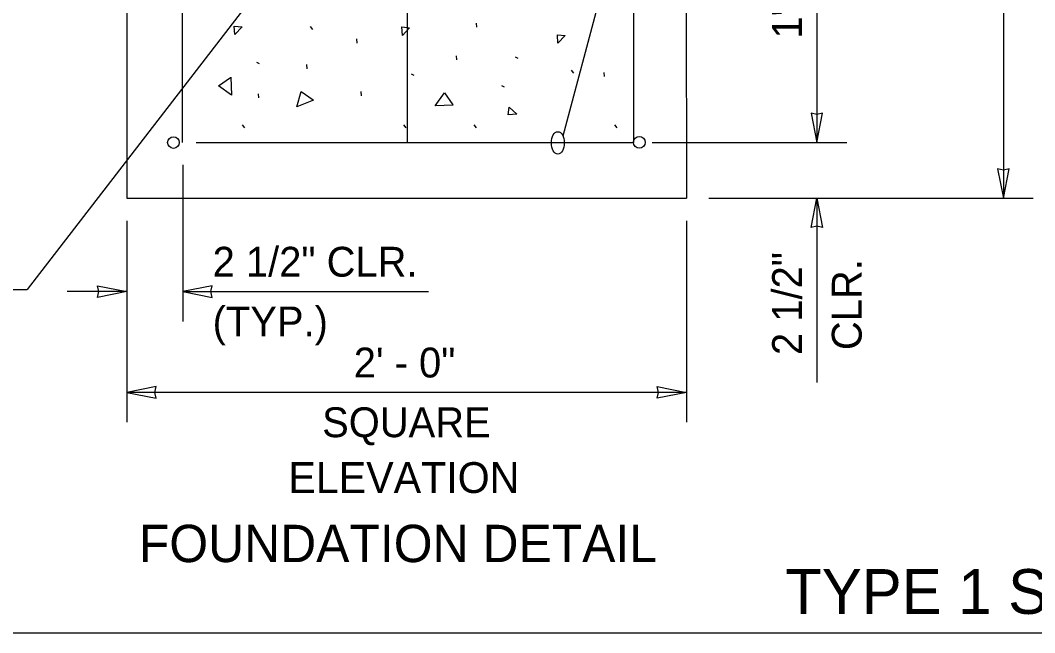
# Model space of a CAD drawing. Extents: x 99862 to 103680, y 99470 to 105076.
# Drawn here: x 101207 to 101751, y 103000 to 103328 of the extents above; entities that cross this region are included whole.
import ezdxf

# ---------------------------------------------------------------- set-up
doc = ezdxf.new("R2010")
doc.units = 0
for name, color, linetype in [('Level 1', 7, 'Continuous'), ('Level 10', 7, 'Continuous'), ('Level 11', 7, 'Continuous'), ('Level 15', 7, 'Continuous'), ('Level 20', 7, 'Continuous'), ('Level 25', 7, 'Continuous'), ('Level 26', 7, 'Continuous')]:
    doc.layers.add(name, color=color, linetype=linetype)

msp = doc.modelspace()

# ---------------------------------------------------------------- linework, layer by layer
at = {"layer": 'Level 1'}
msp.add_line((101564.13, 103688.38), (101564.17, 103232.26), dxfattribs=at)
msp.add_lwpolyline([(101264.13, 103688.38), (101264.17, 103232.26), (101564.17, 103232.26)], dxfattribs=at)
at = {"layer": 'Level 10'}
for centre in [(101289.17, 103262.15), (101538.96, 103262.24)]:
    msp.add_circle(centre, 3.12, dxfattribs=at)
at = {"layer": 'Level 11'}
for p, q in [((101362.5, 103324.26), (101363.69, 103322.64)), ((101451.89, 103323.94), (101451.67, 103326.11)), ((101387.75, 103315.47), (101387.52, 103317.64)), ((101441.19, 103306.51), (101440.96, 103308.68)), ((101472.33, 103308.08), (101473.77, 103307.37)), ((101333.71, 103305.25), (101335.14, 103304.54)), ((101360.9, 103301.72), (101360.67, 103303.9)), ((101416.59, 103298.89), (101418.03, 103298.18)), ((101502.41, 103300.86), (101503.61, 103299.24)), ((101520.29, 103297.57), (101520.06, 103299.75)), ((101465.13, 103292.75), (101466.57, 103292.04)), ((101334.92, 103286.13), (101334.69, 103288.31)), ((101389.99, 103287.24), (101389.76, 103289.41)), ((101326, 103271.62), (101327.19, 103270)), ((101412.51, 103271.62), (101413.7, 103270)), ((101450.21, 103271.62), (101451.4, 103270)), ((101525.61, 103271.62), (101526.81, 103270))]:
    msp.add_line(p, q, dxfattribs=at)
for points in [[(101322.15, 103319.95), (101321.8, 103324.55), (101325.93, 103324.06), (101322.15, 103319.95)], [(101411.95, 103319.48), (101411.6, 103324.08), (101415.74, 103323.58), (101411.95, 103319.48)], [(101495.35, 103315.3), (101495, 103319.9), (101499.13, 103319.41), (101495.35, 103315.3)], [(101319.88, 103297.09), (101320.23, 103287.49), (101313.29, 103292.52), (101319.73, 103297.01)], [(101364.27, 103284.91), (101355.37, 103281.3), (101357.72, 103289.54), (101364.14, 103285.02)], [(101439.11, 103282.2), (101429.51, 103281.85), (101434.54, 103288.79), (101439.03, 103282.34)], [(101473.21, 103277.36), (101468.61, 103277.01), (101469.1, 103281.14), (101473.21, 103277.36)]]:
    msp.add_lwpolyline(points, dxfattribs=at)
at = {"layer": 'Level 15'}
for p, q in [((101734.13, 103694.63), (101734.17, 103232.26)), ((101582.9, 103584.75), (101497.99, 103265.63)), ((101634.13, 103466.58), (101634.17, 103262.24)), ((101362.36, 103380.04), (101210.75, 103183.32)), ((101545.87, 103262.24), (101650.17, 103262.24)), ((101294.17, 103250.15), (101294.17, 103166.26)), ((101576.17, 103232.26), (101750.17, 103232.26)), ((101634.17, 103232.26), (101634.17, 103133.62)), ((101264.17, 103220.26), (101264.17, 103112.26)), ((101564.17, 103220.26), (101564.17, 103112.26)), ((101194.75, 103183.32), (101210.75, 103183.32)), ((101264.17, 103182.26), (101232.17, 103182.26)), ((101294.17, 103182.26), (101425.99, 103182.26)), ((101301.87, 103182.26), (101345.8, 103182.26)), ((101564.17, 103128.26), (101264.17, 103128.26))]:
    msp.add_line(p, q, dxfattribs=at)
for points in [[(101634.17, 103262.24), (101637.26, 103277.96), (101634.17, 103277.23), (101631.09, 103277.96)], [(101734.17, 103232.26), (101737.26, 103247.98), (101734.17, 103247.26), (101731.09, 103247.98)], [(101634.17, 103232.26), (101637.26, 103216.53), (101634.17, 103217.26), (101631.09, 103216.53)], [(101264.17, 103182.26), (101248.45, 103179.17), (101249.17, 103182.26), (101248.45, 103185.34)], [(101294.17, 103182.26), (101309.9, 103179.17), (101309.17, 103182.26), (101309.9, 103185.34)], [(101264.17, 103128.26), (101279.9, 103125.17), (101279.17, 103128.26), (101279.9, 103131.34)], [(101564.17, 103128.26), (101548.45, 103125.17), (101549.18, 103128.26), (101548.45, 103131.34)]]:
    msp.add_lwpolyline(points, close=True, dxfattribs=at)
msp.add_ellipse((101495.26, 103261.95), major_axis=(0, 6), ratio=0.57735, dxfattribs=at)
at = {"layer": 'Level 25'}
for p, q in [((101535.8, 103754.2), (101535.84, 103262.15)), ((101414.42, 103650.5), (101414.46, 103262.15)), ((101293.77, 103618.71), (101293.81, 103262.15)), ((101301.3, 103262.15), (101535.84, 103262.15))]:
    msp.add_line(p, q, dxfattribs=at)
at = {"layer": 'Level 26'}
msp.add_lwpolyline([(99862, 102999.5), (103151, 102999.5), (103151, 105075.5), (99862, 105075.5)], close=True, dxfattribs=at)

# ---------------------------------------------------------------- texts
at = {"layer": 'Level 20'}
for s, p in [('1\' - 3 1/2"', (101626.17, 103317.84)), ('2 1/2" ', (101626.17, 103148.27)), ('CLR.', (101658.17, 103150.91))]:
    msp.add_text(s, height=16, rotation=90, dxfattribs=at).set_placement(p)
for s, height, p in [('2 1/2" CLR.', 16, (101310.17, 103190.26)), ('(TYP.)', 16, (101310.17, 103158.26)), ('2\' - 0"', 16, (101385.84, 103136.26)), ('SQUARE', 16, (101368.89, 103104.26)), ('ELEVATION', 16.5, (101350.82, 103074.38)), ('FOUNDATION DETAIL', 20, (101270.6, 103037.32)), ('TYPE 1 SIGNAL STANDARD DETAILS', 24, (101617.22, 103009.58))]:
    msp.add_text(s, height=height, dxfattribs=at).set_placement(p)

doc.saveas('drawing.dxf')
